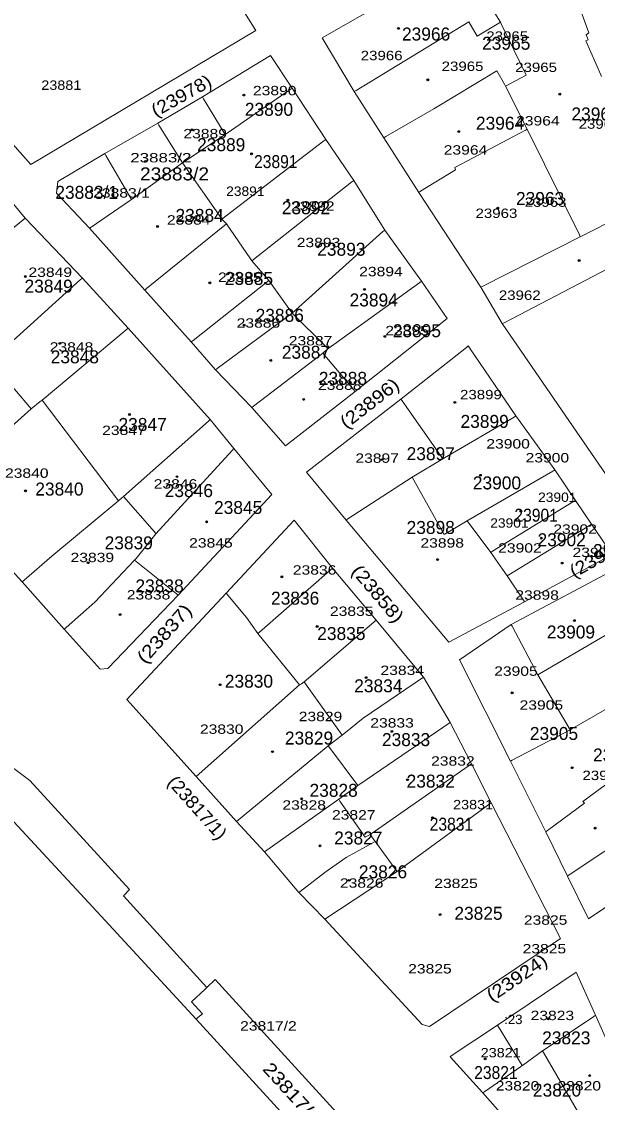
# Model space of a CAD drawing. Extents: x 649608 to 651081, y 237980 to 241202.
# Drawn here: x 650489.8 to 650649.6, y 238207.6 to 238507.5 of the extents above; entities that cross this region are included whole.
import ezdxf

# ---------------------------------------------------------------- set-up
doc = ezdxf.new("R2010")
doc.units = 0
doc.header["$PDMODE"] = 32
doc.header["$PDSIZE"] = 0.5
for name, color, linetype in [('19', 7, 'Continuous'), ('20', 7, 'Continuous'), ('6', 7, 'Continuous')]:
    doc.layers.add(name, color=color, linetype=linetype)
doc.layers.add('3', color=7, linetype='Continuous', lineweight=13)
doc.layers.add('5', color=7, linetype='Continuous', lineweight=13)

msp = doc.modelspace()

# ---------------------------------------------------------------- linework, layer by layer
at = {"layer": '3'}
for p, q in [((650568.91, 238382.456), (650595.07, 238402.789)), ((650565.448, 238369.168), (650546.564, 238348.941))]:
    msp.add_line(p, q, dxfattribs=at)
for points in [[(650554.863, 238505.063), (650547.107, 238517.326), (650525.879, 238552.125), (650514.565, 238573.659)], [(650615.232, 238519.416), (650613.655, 238523.18), (650601.449, 238518.058), (650584.454, 238509.394), (650573.208, 238503.022)], [(650490.784, 238452.952), (650486.321, 238458.459), (650479, 238466.318), (650462.01, 238485.142), (650450.302, 238498.482), (650440.389, 238509.304)], [(650463.677, 238499.933), (650465.462, 238498.038), (650485.053, 238476.157), (650492.425, 238467.844), (650554.863, 238505.063)], [(650573.208, 238503.022), (650582.152, 238488.127), (650590.385, 238475.32), (650600.043, 238460.139), (650617.299, 238433.842), (650623.21, 238423.714), (650654.029, 238378.774), (650670.572, 238354.523), (650679.086, 238341.791), (650687.498, 238329.514), (650694.786, 238317.819)], [(650377.979, 238500.018), (650389.177, 238475.141), (650397.805, 238455.67), (650409.436, 238441.95), (650424.433, 238424.542), (650438.259, 238409.104), (650446.37, 238399.327), (650466.957, 238377.142), (650490.018, 238352.102), (650501.675, 238338.963)], [(650540.016, 238486.629), (650558.882, 238498.097), (650564.871, 238489.028), (650574.226, 238474.831), (650581.975, 238463.439), (650590.588, 238449.697), (650600.837, 238435.474), (650607.901, 238425.185), (650582.368, 238404.897), (650563.098, 238389.83)], [(650508.649, 238450.182), (650499.491, 238459.961), (650499.881, 238463.167), (650512.91, 238470.904), (650527.627, 238479.321), (650540.016, 238486.629)], [(650533.243, 238348.398), (650559.249, 238376.268), (650548.742, 238389.052), (650542.187, 238397.111), (650519.382, 238422.454), (650506.679, 238436.376), (650490.784, 238452.952)], [(650563.098, 238389.83), (650563.086, 238389.845), (650553.673, 238400.407), (650543.596, 238410.893), (650536.913, 238418.65), (650523.98, 238433.026), (650508.649, 238450.182)], [(650595.07, 238402.789), (650613.272, 238417.106), (650613.787, 238417.512)], [(650613.787, 238417.512), (650614.114, 238417.034), (650626.967, 238398.087), (650637.752, 238383.107), (650643.512, 238374.619), (650647.922, 238368.026), (650653.658, 238359.639), (650629.394, 238346.511)], [(650629.394, 238346.511), (650608.382, 238335.323), (650579.892, 238369.179), (650568.91, 238382.456)], [(650601.004, 238229.183), (650603.053, 238228.697), (650639.394, 238253.044), (650620.154, 238290.73), (650614.628, 238301.591), (650608.771, 238313.057), (650601.357, 238325.586), (650588.171, 238341.452), (650576.133, 238355.853), (650565.448, 238369.168)], [(650625.649, 238340.229), (650655.926, 238356.355), (650664.083, 238344.431), (650674, 238330.436), (650683.612, 238317.325), (650691.539, 238305.2), (650698.955, 238293.605)], [(650501.675, 238338.963), (650511.598, 238327.871), (650513.721, 238328.021), (650533.243, 238348.398)], [(650546.564, 238348.941), (650519.047, 238319.432), (650538.229, 238298.082), (650549.428, 238285.575), (650557.183, 238277.135), (650566.773, 238265.867), (650573.942, 238258.438), (650601.004, 238229.183)], [(650625.495, 238302.287), (650611.312, 238330.423), (650625.649, 238340.229)], [(650680.881, 238281.304), (650647.164, 238258.567), (650641.308, 238270.413), (650635.299, 238282.662), (650625.495, 238302.287)], [(650541.23, 238239.462), (650518.067, 238264.88), (650519.809, 238266.721), (650492.156, 238296.941), (650485.494, 238301.946)], [(650484.19, 238289.275), (650511.92, 238259.307), (650538.247, 238230.705)], [(650608.764, 238220.3), (650621.863, 238229.07), (650643.724, 238243.705)], [(650643.724, 238243.705), (650648.977, 238232.009), (650649.081, 238231.778)], [(650598.74, 238168.998), (650574.582, 238195.781), (650578.476, 238199.463), (650576.052, 238201.939), (650578.203, 238203.679), (650543.51, 238241.706), (650541.23, 238239.462)], [(650538.247, 238230.705), (650571.563, 238194.27), (650596.69, 238166.88), (650598.74, 238168.998)], [(650649.081, 238231.778), (650661.143, 238204.909), (650661.217, 238204.732)], [(650617.856, 238210.25), (650617.742, 238210.38), (650608.865, 238220.184), (650608.764, 238220.3)], [(650634.266, 238191.546), (650634.118, 238191.708), (650617.856, 238210.25)]]:
    msp.add_lwpolyline(points, dxfattribs=at)
at = {"layer": '5'}
for p, q in [((650534.508, 238468.358), (650520.298, 238458.148)), ((650666.513, 238458.735), (650644.862, 238447.851)), ((650564.873, 238426.624), (650558.449, 238435.668))]:
    msp.add_line(p, q, dxfattribs=at)
for points in [[(650637.963, 238526.941), (650638.166, 238526.441), (650639.331, 238523.578), (650640.223, 238523.816), (650647.193, 238504.378), (650646.46, 238503.894), (650647.011, 238502.484)], [(650615.232, 238519.416), (650615.543, 238518.916), (650622.678, 238507.426)], [(650582.152, 238488.127), (650582.652, 238488.431), (650613.964, 238507.468)], [(650622.678, 238507.426), (650616.207, 238503.536), (650613.964, 238507.468)], [(650624.084, 238489.651), (650629.817, 238492.7), (650622.92, 238506.926), (650622.678, 238507.426)], [(650650.781, 238492.275), (650650.557, 238492.775), (650646.354, 238502.163), (650647.011, 238502.484)], [(650590.385, 238475.32), (650590.885, 238475.609), (650604.258, 238483.334), (650621.664, 238493.894), (650623.799, 238490.151), (650624.084, 238489.651)], [(650546.336, 238476.222), (650546.836, 238476.567), (650564.371, 238488.683), (650564.871, 238489.028)], [(650644.862, 238447.851), (650644.615, 238448.351), (650630.119, 238477.654), (650624.084, 238489.651)], [(650546.336, 238476.222), (650540.32, 238486.129), (650540.016, 238486.629)], [(650534.508, 238468.358), (650527.941, 238478.821), (650527.627, 238479.321)], [(650545.419, 238452.67), (650545.071, 238453.17), (650534.508, 238468.358), (650546.336, 238476.222)], [(650600.043, 238460.139), (650600.543, 238460.447), (650610.232, 238466.415), (650610.086, 238467.02), (650629.619, 238477.389), (650630.119, 238477.654)], [(650545.419, 238452.67), (650573.726, 238474.446), (650574.226, 238474.831)], [(650520.298, 238458.148), (650513.2, 238470.404), (650512.91, 238470.904)], [(650553.73, 238441.176), (650581.475, 238463.045), (650581.975, 238463.439)], [(650520.298, 238458.148), (650519.798, 238457.806), (650509.149, 238450.524), (650508.649, 238450.182)], [(650473.575, 238438.984), (650490.284, 238452.546), (650490.784, 238452.952)], [(650546.643, 238451.432), (650546.149, 238451.932), (650545.419, 238452.67)], [(650546.643, 238451.432), (650524.48, 238433.432), (650523.98, 238433.026)], [(650553.73, 238441.176), (650553.384, 238441.676), (650546.643, 238451.432)], [(650590.588, 238449.697), (650590.088, 238449.248), (650564.873, 238426.624)], [(650644.862, 238447.851), (650617.799, 238434.096), (650617.299, 238433.842)], [(650671.477, 238448.077), (650670.977, 238447.836), (650652.591, 238438.983), (650623.71, 238423.974), (650623.21, 238423.714)], [(650558.449, 238435.668), (650558.021, 238436.168), (650553.73, 238441.176)], [(650489.338, 238420.666), (650506.179, 238435.923), (650506.679, 238436.376)], [(650558.449, 238435.668), (650537.413, 238419.045), (650536.913, 238418.65)], [(650600.837, 238435.474), (650600.337, 238435.114), (650574.799, 238416.744), (650573.441, 238415.559)], [(650564.873, 238426.624), (650544.096, 238411.263), (650543.596, 238410.893)], [(650564.873, 238426.624), (650574.299, 238417.242), (650574.799, 238416.744)], [(650495.489, 238402.509), (650518.882, 238422.037), (650519.382, 238422.454)], [(650492.493, 238400.089), (650492.064, 238400.589), (650481.066, 238413.404), (650489.338, 238420.666)], [(650573.441, 238415.559), (650572.941, 238415.176), (650554.173, 238400.79), (650553.673, 238400.407)], [(650573.441, 238415.559), (650581.949, 238405.397), (650582.368, 238404.897)], [(650495.489, 238402.509), (650494.989, 238402.105), (650492.493, 238400.089)], [(650518.112, 238375.778), (650517.612, 238375.332), (650516.755, 238374.568), (650495.489, 238402.509)], [(650606.72, 238386.217), (650595.421, 238402.289), (650595.07, 238402.789)], [(650492.493, 238400.089), (650467.457, 238377.591), (650466.957, 238377.142)], [(650606.72, 238386.217), (650607.22, 238386.51), (650626.467, 238397.794), (650626.967, 238398.087)], [(650542.187, 238397.111), (650541.687, 238396.668), (650518.112, 238375.778)], [(650527.09, 238365.394), (650548.284, 238388.552), (650548.742, 238389.052)], [(650598.197, 238381.126), (650598.697, 238381.425), (650606.72, 238386.217)], [(650613.461, 238368.994), (650613.961, 238369.284), (650637.252, 238382.817), (650637.752, 238383.107)], [(650598.197, 238381.126), (650580.392, 238369.505), (650579.892, 238369.179)], [(650613.461, 238368.994), (650607.061, 238365.188), (650598.197, 238381.126)], [(650516.755, 238374.568), (650516.255, 238374.153), (650498.239, 238359.213), (650490.518, 238352.534), (650490.018, 238352.102)], [(650518.112, 238375.778), (650526.658, 238365.894), (650527.09, 238365.394)], [(650620.013, 238360.228), (650620.513, 238360.534), (650643.012, 238374.313), (650643.512, 238374.619)], [(650629.394, 238346.511), (650629.057, 238347.011), (650624.526, 238353.735), (650620.013, 238360.228), (650613.461, 238368.994)], [(650521.17, 238358.079), (650521.575, 238358.579), (650527.09, 238365.394)], [(650624.526, 238353.735), (650625.026, 238354.04), (650647.422, 238367.721), (650647.922, 238368.026)], [(650521.17, 238358.079), (650510.153, 238346.402), (650502.175, 238339.402), (650501.675, 238338.963)], [(650533.243, 238348.398), (650532.743, 238348.799), (650521.17, 238358.079)], [(650555.336, 238337.698), (650555.836, 238338.134), (650576.133, 238355.853)], [(650546.564, 238348.941), (650552.201, 238342.144), (650555.336, 238337.698), (650566.966, 238323.474), (650538.229, 238298.082)], [(650633.06, 238326.261), (650633.56, 238326.554), (650663.583, 238344.138), (650664.083, 238344.431)], [(650566.966, 238323.474), (650567.466, 238323.789), (650568.246, 238324.281), (650588.171, 238341.452)], [(650625.649, 238340.229), (650625.914, 238339.729), (650633.06, 238326.261), (650642.003, 238311.005)], [(650578.749, 238309.502), (650568.601, 238323.781), (650568.246, 238324.281)], [(650578.749, 238309.502), (650579.249, 238309.902), (650584.639, 238314.217), (650601.357, 238325.586)], [(650642.003, 238311.005), (650642.503, 238311.292), (650654.699, 238318.288)], [(650583.144, 238295.538), (650583.644, 238295.88), (650608.771, 238313.057)], [(650549.428, 238285.575), (650574.934, 238306.578), (650578.749, 238309.502)], [(650642.003, 238311.005), (650625.995, 238302.551), (650625.495, 238302.287)], [(650574.934, 238306.578), (650575.306, 238306.078), (650583.144, 238295.538), (650577.819, 238291.706), (650557.183, 238277.135)], [(650586.568, 238281.953), (650587.068, 238282.303), (650614.628, 238301.591)], [(650635.299, 238282.662), (650635.799, 238283.032), (650646.025, 238290.6), (650645.528, 238291.118), (650653.596, 238296.986)], [(650641.308, 238270.413), (650641.808, 238270.746), (650661.302, 238283.747), (650660.819, 238284.934), (650672.084, 238293.127)], [(650620.154, 238290.73), (650594.064, 238271.646), (650573.942, 238258.438)], [(650586.568, 238281.953), (650585.161, 238281.248), (650578.17, 238291.206), (650577.819, 238291.706)], [(650566.773, 238265.867), (650574.327, 238271.716), (650579.908, 238275.548), (650587.945, 238280.008), (650586.568, 238281.953)], [(650587.945, 238280.008), (650588.311, 238279.508), (650593.698, 238272.146), (650594.064, 238271.646)], [(650538.247, 238230.705), (650538.747, 238231.121), (650540.065, 238232.218), (650536.978, 238235.528), (650540.73, 238238.999), (650541.23, 238239.462)], [(650649.081, 238231.778), (650648.581, 238231.443), (650634.512, 238222.026), (650634.341, 238221.901)], [(650628.767, 238217.855), (650622.171, 238228.57), (650621.863, 238229.07)], [(650634.341, 238221.901), (650628.776, 238217.841), (650628.767, 238217.855)], [(650634.341, 238221.901), (650634.631, 238221.401), (650647.745, 238198.783), (650648.035, 238198.283)], [(650628.767, 238217.855), (650628.267, 238217.506), (650618.356, 238210.599), (650617.856, 238210.25)]]:
    msp.add_lwpolyline(points, dxfattribs=at)
at = {"layer": '6'}
for p in [(650594.415, 238505.653), (650602.534, 238491.394), (650551.527, 238487.159), (650639.147, 238487.396), (650537.169, 238477.493), (650611.119, 238477.016), (650553.652, 238470.849), (650524.22, 238468.734), (650509.236, 238460.543), (650563.715, 238458.003), (650621.94, 238455.748), (650527.563, 238450.692), (650572.004, 238445.031), (650644.534, 238441.224), (650490.855, 238436.809), (650542.058, 238435.041), (650584.964, 238433.22), (650551.561, 238423.28), (650590.596, 238420.185), (650500.445, 238418.232), (650558.958, 238413.515), (650568.104, 238402.694), (650610.062, 238401.864), (650519.73, 238398.511), (650589.889, 238385.984), (650532.946, 238381.252), (650617.137, 238381.637), (650490.905, 238377.305), (650628.377, 238371.667), (650541.174, 238368.725), (650634.041, 238364.177), (650508.305, 238357.37), (650605.258, 238358.224), (650639.793, 238357.268), (650562.059, 238353.433), (650517.147, 238342.975), (650643.213, 238341.308), (650571.841, 238339.663), (650544.893, 238323.511), (650585.415, 238325.477), (650625.962, 238321.258), (650592.597, 238310.562), (650559.454, 238304.928), (650642.587, 238300.475), (650596.895, 238297.152), (650567.542, 238291.856), (650603.883, 238286.618), (650648.965, 238283.699), (650572.632, 238278.786), (650580.74, 238269.223), (650605.937, 238259.713), (650635.993, 238230.773), (650618.498, 238219.66), (650647.462, 238215.03)]:
    msp.add_point(p, dxfattribs=at)

# ---------------------------------------------------------------- texts
at = {"layer": '19'}
for s, p in [('23966', (650595.376, 238502.292)), ('23965', (650617.607, 238499.733)), ('23890', (650551.771, 238481.388)), ('23967', (650642.402, 238480.109)), ('23964', (650615.897, 238477.549)), ('23889', (650538.519, 238471.576)), ('23883/1', (650499.187, 238458.351)), ('23963', (650627.012, 238456.646)), ('23884', (650532.532, 238451.952)), ('23892', (650562.032, 238454.085)), ('23893', (650571.865, 238442.567)), ('23885', (650546.213, 238434.461)), ('23849', (650490.637, 238432.327)), ('23894', (650580.842, 238428.489)), ('23886', (650554.765, 238424.223)), ('23895', (650592.813, 238419.957)), ('23848', (650497.904, 238412.703)), ('23887', (650562.032, 238413.984)), ('23888', (650572.292, 238406.732)), ('23899', (650611.622, 238394.787)), ('23847', (650516.715, 238393.933)), ('23897', (650596.659, 238385.828)), ('23900', (650615.041, 238377.722)), ('23840', (650493.629, 238376.015)), ('23846', (650529.54, 238375.588)), ('23845', (650543.22, 238370.896)), ('23898', (650596.659, 238365.351)), ('23902', (650632.998, 238361.938)), ('23839', (650512.868, 238361.084)), ('23903', (650648.388, 238358.951)), ('23838', (650521.417, 238349.139)), ('23836', (650559.04, 238345.727)), ('23835', (650571.864, 238335.915)), ('23909', (650635.563, 238336.341)), ('23830', (650546.213, 238322.69)), ('23834', (650582.123, 238321.411)), ('23905', (650630.859, 238308.185)), ('23829', (650562.886, 238306.906)), ('23833', (650589.82, 238306.479)), ('23906', (650648.388, 238302.212)), ('23832', (650596.66, 238294.961)), ('23828', (650569.726, 238292.401)), ('23827', (650576.567, 238279.176)), ('23826', (650583.407, 238269.791)), ('23825', (650609.912, 238258.272)), ('23823', (650634.28, 238223.717)), ('23820', (650631.714, 238209.212))]:
    msp.add_text(s, height=3.6, dxfattribs=at).set_placement(p)
for s, rotation, width, p in [('(23978)', 29.309, 1.1, (650527.074, 238480.942)), ('(23896)', 37.815, 1.15, (650579.933, 238394.369)), ('(23904)', 29.304, 1.1, (650643.18, 238353.038)), ('(23858)', 310.239, 1.15, (650581.125, 238354.887)), ('(23837)', 48.304, 1.2, (650524.135, 238329.063)), ('(23817/1)', 311.699, 1.05, (650530.061, 238296.294)), ('(23924)', 34.231, 1.15, (650620.371, 238235.333)), ('23817/2', 312.44, 1.2, (650556.482, 238216.692))]:
    msp.add_text(s, height=3.6, rotation=rotation, dxfattribs=dict(at, width=width)).set_placement(p)
for s, width, p in [('23891', 0.9, (650554.337, 238466.884)), ('23883/2', 1.1, (650522.699, 238463.471)), ('23901', 0.9, (650626.585, 238368.763)), ('23831', 0.9, (650603.072, 238283.016)), ('23821', 0.9, (650615.418, 238214.082))]:
    msp.add_text(s, height=3.6, dxfattribs=dict(at, width=width)).set_placement(p)
at = {"layer": '20'}
for s, width, p in [('23965', 1.2, (650618.777, 238502.222)), ('23966', 1.2, (650583.936, 238496.83)), ('23965', 1.2, (650606.389, 238493.846)), ('23965', 1.2, (650626.791, 238493.553)), ('23881', 1.15, (650495.285, 238488.6)), ('23890', 1.25, (650554.016, 238487.093)), ('23964', 1.25, (650627.042, 238478.714)), ('23967', 1.2, (650644.394, 238477.799)), ('23889', 1.25, (650534.718, 238475.152)), ('23964', 1.25, (650606.962, 238470.635)), ('23883/2', 1.35, (650519.98, 238468.465)), ('23883/1', 1.25, (650509.685, 238458.702)), ('23891', 1.1, (650546.592, 238459.176)), ('23963', 1.2, (650629.423, 238456.138)), ('23892', 1.25, (650564.582, 238455.028)), ('23963', 1.2, (650615.783, 238453.046)), ('23884', 1.25, (650530.15, 238451.2)), ('23893', 1.25, (650566.179, 238444.942)), ('23849', 1.25, (650491.74, 238436.679)), ('23885', 1.25, (650544.34, 238435.305)), ('23894', 1.25, (650583.505, 238436.874)), ('23962', 1.2, (650622.256, 238430.315)), ('23886', 1.25, (650549.498, 238422.602)), ('23895', 1.25, (650590.755, 238420.495)), ('23887', 1.25, (650563.96, 238417.68)), ('23848', 1.25, (650497.636, 238415.949)), ('23888', 1.25, (650572.066, 238405.335)), ('23899', 1.2, (650611.49, 238402.725)), ('23847', 1.25, (650512.184, 238392.818)), ('23900', 1.25, (650618.78, 238389.063)), ('23897', 1.25, (650582.452, 238385.094)), ('23900', 1.25, (650629.676, 238385.2)), ('23840', 1.25, (650485.214, 238380.93)), ('23846', 1.25, (650526.486, 238377.939)), ('23901', 1.1, (650633.154, 238374.24)), ('23901', 1.1, (650619.866, 238367.094)), ('23902', 1.25, (650637.379, 238365.398)), ('23845', 1.25, (650536.321, 238361.575)), ('23898', 1.25, (650600.504, 238361.555)), ('23902', 1.25, (650622.069, 238360.171)), ('23839', 1.25, (650503.404, 238357.523)), ('23903', 1.25, (650642.705, 238358.951)), ('23836', 1.25, (650565.089, 238354.06)), ('23838', 1.25, (650519.012, 238347.166)), ('23898', 1.25, (650626.828, 238347.098)), ('23835', 1.25, (650575.389, 238342.614)), ('23834', 1.25, (650589.412, 238326.21)), ('23905', 1.25, (650620.957, 238325.987)), ('23905', 1.25, (650628.006, 238316.577)), ('23829', 1.25, (650566.722, 238313.394)), ('23833', 1.25, (650586.586, 238311.625)), ('23830', 1.25, (650539.309, 238309.883)), ('23832', 1.25, (650603.459, 238301.051)), ('23906', 1.2, (650645.458, 238297.052)), ('23828', 1.25, (650562.198, 238288.84)), ('23831', 1.15, (650609.562, 238288.942)), ('23827', 1.25, (650575.954, 238286.1)), ('23826', 1.25, (650578.153, 238267.177)), ('23825', 1.25, (650604.332, 238267.084)), ('23825', 1.25, (650629.19, 238256.896)), ('23825', 1.25, (650628.851, 238248.951)), ('23825', 1.25, (650597.091, 238243.378)), ('23817/2', 1.25, (650550.459, 238227.534)), (':23', 1.05, (650623.74, 238229.324)), ('23823', 1.25, (650631.068, 238230.429)), ('23821', 1.15, (650617.216, 238220.102)), ('23820', 1.25, (650621.4, 238210.897)), ('23820', 1.25, (650638.523, 238210.91))]:
    msp.add_text(s, height=2.6, dxfattribs=dict(at, width=width)).set_placement(p)

doc.saveas('drawing.dxf')
